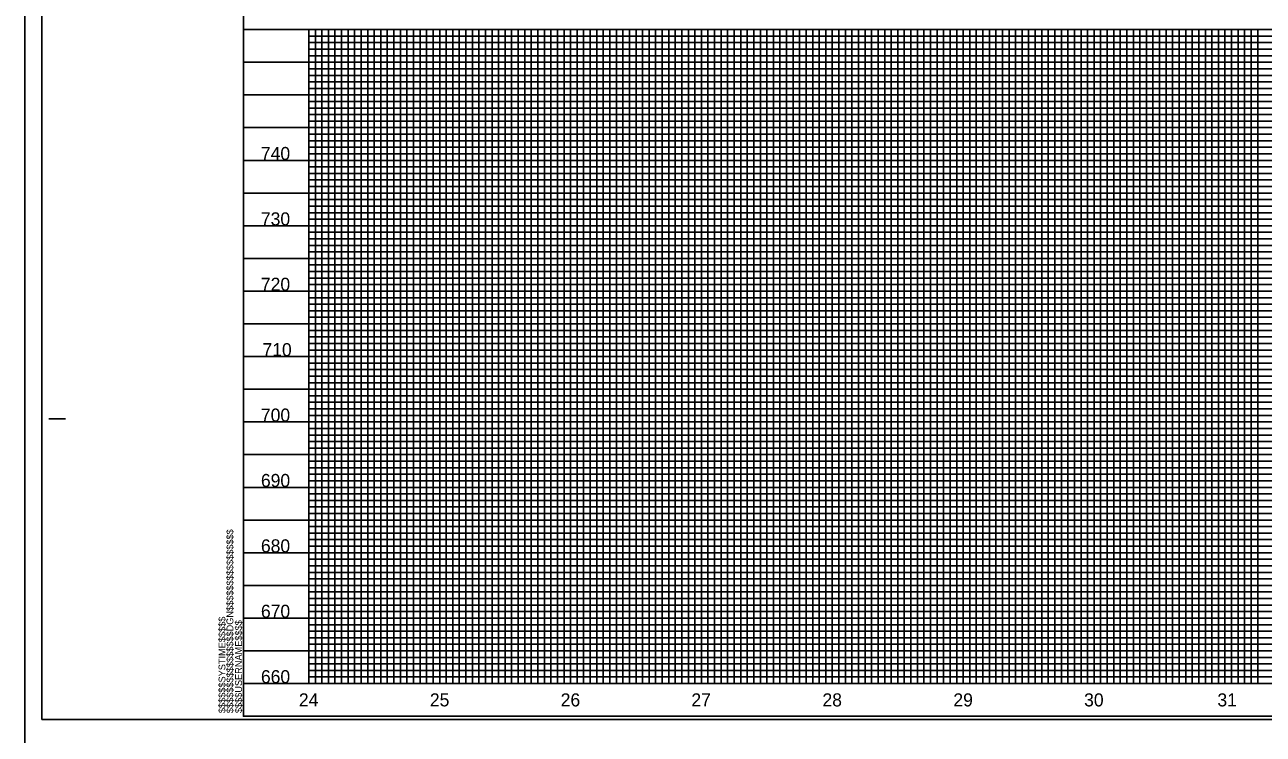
# Model space of a CAD drawing. Extents: x 1754992 to 1757273, y 732111 to 735411.
# Drawn here: x 1755181 to 1756127, y 734322 to 734864 of the extents above; entities that cross this region are included whole.
import ezdxf

# ---------------------------------------------------------------- set-up
doc = ezdxf.new("R2010")
doc.units = 0
for name, color, linetype in [('Prop DSN Text', 7, 'Continuous'), ('Scratch_Level_3', 7, 'Continuous'), ('Sheet Cutting Line CELL', 7, 'Continuous'), ('Sheet DOT Grid CELL', 7, 'Continuous'), ('Sheet Plot Border Inside CELL', 7, 'Continuous'), ('Sheet Plot Border Outside CELL', 7, 'Continuous'), ('Sheet Profile CELL', 7, 'Continuous'), ('Sheet Profile Grid Major CELL', 7, 'Continuous'), ('Sheet Profile Grid Middle CELL', 7, 'Continuous'), ('Sheet Profile Grid Minor CELL', 7, 'Continuous')]:
    doc.layers.add(name, color=color, linetype=linetype)

msp = doc.modelspace()

# ---------------------------------------------------------------- linework, layer by layer
at = {"layer": 'Scratch_Level_3'}
msp.add_lwpolyline([(1755397.67, 734860.78), (1756797.67, 734860.78), (1756797.67, 734360.78), (1755397.67, 734360.78)], close=True, dxfattribs=at)
at = {"layer": 'Sheet Cutting Line CELL'}
msp.add_line((1755180.67, 735410.78), (1755180.67, 734310.78), dxfattribs=at)
at = {"layer": 'Sheet DOT Grid CELL'}
for p, q in [((1755347.67, 734860.78), (1756847.56, 734860.78)), ((1755397.67, 734860.78), (1755397.67, 734360.78)), ((1755447.67, 734860.78), (1755447.67, 734360.78)), ((1755497.67, 734860.78), (1755497.67, 734360.78)), ((1755547.67, 734860.78), (1755547.67, 734360.78)), ((1755597.67, 734860.78), (1755597.67, 734360.78)), ((1755647.67, 734860.78), (1755647.67, 734360.78)), ((1755697.67, 734860.78), (1755697.67, 734360.78)), ((1755747.67, 734860.78), (1755747.67, 734360.78)), ((1755797.67, 734860.78), (1755797.67, 734360.78)), ((1755847.67, 734860.78), (1755847.67, 734360.78)), ((1755897.67, 734860.78), (1755897.67, 734360.78)), ((1755947.67, 734860.78), (1755947.67, 734360.78)), ((1755997.67, 734860.78), (1755997.67, 734360.78)), ((1756047.67, 734860.78), (1756047.67, 734360.78)), ((1756097.67, 734860.78), (1756097.67, 734360.78)), ((1755347.67, 734810.78), (1756847.56, 734810.78)), ((1755347.67, 734760.78), (1756847.56, 734760.78)), ((1755347.67, 734710.78), (1756847.56, 734710.78)), ((1755347.67, 734660.78), (1756847.56, 734660.78)), ((1755347.67, 734610.78), (1756847.56, 734610.78)), ((1755347.67, 734560.78), (1756847.56, 734560.78)), ((1755347.67, 734510.78), (1756847.56, 734510.78)), ((1755347.67, 734460.78), (1756847.56, 734460.78)), ((1755347.67, 734410.78), (1756847.56, 734410.78))]:
    msp.add_line(p, q, dxfattribs=at)
at = {"layer": 'Sheet Plot Border Inside CELL'}
msp.add_lwpolyline([(1755193.67, 734333.23), (1756860.17, 734333.23), (1756860.17, 735388.33), (1755193.67, 735388.33)], close=True, dxfattribs=at)
at = {"layer": 'Sheet Plot Border Outside CELL'}
msp.add_lwpolyline([(1755180.67, 734310.78), (1756864.67, 734310.78), (1756864.67, 735410.78), (1755180.67, 735410.78)], close=True, dxfattribs=at)
at = {"layer": 'Sheet Profile CELL'}
for p, q in [((1755347.67, 734860.78), (1756847.67, 734860.78)), ((1755199.17, 734563.28), (1755211.67, 734563.28)), ((1756847.67, 734360.78), (1755347.67, 734360.78)), ((1755347.67, 734335.78), (1756847.67, 734335.78)), ((1755347.67, 734335.78), (1755347.67, 734335.78)), ((1755347.67, 734335.78), (1755347.67, 734335.78)), ((1755347.67, 734335.78), (1755347.67, 734335.78)), ((1755347.67, 734335.78), (1755347.67, 734335.78)), ((1755347.67, 734335.78), (1755347.67, 734335.78)), ((1755347.67, 734335.78), (1755347.67, 734335.78)), ((1755347.67, 734335.78), (1755347.67, 734335.78))]:
    msp.add_line(p, q, dxfattribs=at)
msp.add_lwpolyline([(1756847.67, 735385.78), (1755347.67, 735385.78), (1755347.67, 734335.78), (1756847.67, 734335.78)], close=True, dxfattribs=at)
msp.add_lwpolyline([(1755385.17, 734335.78), (1755385.17, 734335.78)], dxfattribs=at)
at = {"layer": 'Sheet Profile Grid Major CELL'}
for p, q in [((1755847.67, 734860.78), (1755897.67, 734860.78)), ((1755947.67, 734860.78), (1755997.67, 734860.78)), ((1756047.67, 734860.78), (1756097.67, 734860.78)), ((1755347.67, 734360.78), (1755347.67, 734360.78))]:
    msp.add_line(p, q, dxfattribs=at)
for points in [[(1755397.67, 734860.78), (1755397.67, 734360.78), (1755447.67, 734360.78), (1755447.67, 734860.78), (1755497.67, 734860.78), (1755497.67, 734360.78), (1755547.67, 734360.78), (1755547.67, 734860.78), (1755597.67, 734860.78), (1755597.67, 734360.78), (1755647.67, 734360.78), (1755647.67, 734860.78), (1755697.67, 734860.78), (1755697.67, 734360.78), (1755747.67, 734360.78), (1755747.67, 734860.78), (1755797.67, 734860.78), (1755797.67, 734360.78), (1755847.67, 734360.78), (1755847.67, 734860.78), (1755897.67, 734860.78), (1755897.67, 734360.78), (1755947.67, 734360.78), (1755947.67, 734860.78), (1755997.67, 734860.78), (1755997.67, 734360.78), (1756047.67, 734360.78), (1756047.67, 734860.78), (1756097.67, 734860.78), (1756097.67, 734360.78), (1756147.67, 734360.78)], [(1756847.67, 734810.78), (1755347.67, 734810.78)], [(1756847.67, 734760.78), (1755347.67, 734760.78), (1755347.67, 734710.78), (1756847.67, 734710.78)], [(1756847.67, 734660.78), (1755347.67, 734660.78), (1755347.67, 734610.78), (1756847.67, 734610.78)], [(1756847.67, 734560.78), (1755347.67, 734560.78), (1755347.67, 734510.78), (1756847.67, 734510.78)], [(1756847.67, 734460.78), (1755347.67, 734460.78), (1755347.67, 734460.78), (1755347.67, 734410.78), (1756847.67, 734410.78)], [(1756847.67, 734360.78), (1755347.67, 734360.78)]]:
    msp.add_lwpolyline(points, dxfattribs=at)
at = {"layer": 'Sheet Profile Grid Middle CELL'}
for points in [[(1755372.67, 734860.78), (1755422.67, 734860.78), (1755422.67, 734360.78), (1755472.67, 734360.78), (1755472.67, 734860.78), (1755522.67, 734860.78), (1755522.67, 734360.78), (1755572.67, 734360.78), (1755572.67, 734860.78), (1755622.67, 734860.78), (1755622.67, 734360.78), (1755672.67, 734360.78), (1755672.67, 734860.78), (1755722.67, 734860.78), (1755722.67, 734360.78), (1755772.67, 734360.78), (1755772.67, 734860.78), (1755822.67, 734860.78), (1755822.67, 734360.78), (1755872.67, 734360.78), (1755872.67, 734860.78), (1755922.67, 734860.78), (1755922.67, 734360.78), (1755972.67, 734360.78), (1755972.67, 734360.78), (1755972.67, 734860.78), (1756022.67, 734860.78), (1756022.67, 734360.78), (1756072.67, 734360.78), (1756072.67, 734860.78), (1756122.67, 734860.78), (1756122.67, 734360.78), (1756172.67, 734360.78)], [(1755347.67, 734835.78), (1756847.67, 734835.78)], [(1756847.67, 734785.78), (1755347.67, 734785.78), (1755347.67, 734735.78), (1756847.67, 734735.78)], [(1756847.67, 734685.78), (1755347.67, 734685.78), (1755347.67, 734635.78), (1756847.67, 734635.78)], [(1756847.67, 734585.78), (1755347.67, 734585.78), (1755347.67, 734535.78), (1756847.67, 734535.78)], [(1756847.67, 734485.78), (1755347.67, 734485.78), (1755347.67, 734435.78), (1756847.67, 734435.78)], [(1756847.67, 734385.78), (1755347.67, 734385.78)]]:
    msp.add_lwpolyline(points, dxfattribs=at)
at = {"layer": 'Sheet Profile Grid Minor CELL'}
for p, q in [((1755397.67, 734855.78), (1756797.67, 734855.78)), ((1756797.67, 734850.78), (1755397.67, 734850.78)), ((1755397.67, 734845.78), (1756797.67, 734845.78)), ((1756797.67, 734840.78), (1755397.67, 734840.78)), ((1755397.67, 734830.78), (1756797.67, 734830.78)), ((1756797.67, 734825.78), (1755397.67, 734825.78)), ((1755397.67, 734820.78), (1756797.67, 734820.78)), ((1756797.67, 734815.78), (1755397.67, 734815.78)), ((1755397.67, 734805.78), (1756797.67, 734805.78)), ((1756797.67, 734800.78), (1755397.67, 734800.78)), ((1755397.67, 734795.78), (1756797.67, 734795.78)), ((1756797.67, 734790.78), (1755397.67, 734790.78)), ((1755397.67, 734780.78), (1756797.67, 734780.78)), ((1756797.67, 734775.78), (1755397.67, 734775.78)), ((1755397.67, 734770.78), (1756797.67, 734770.78)), ((1756797.67, 734765.78), (1755397.67, 734765.78)), ((1755397.67, 734755.78), (1756797.67, 734755.78)), ((1756797.67, 734750.78), (1755397.67, 734750.78)), ((1755397.67, 734745.78), (1756797.67, 734745.78)), ((1756797.67, 734740.78), (1755397.67, 734740.78)), ((1755397.67, 734730.78), (1756797.67, 734730.78)), ((1756797.67, 734725.78), (1755397.67, 734725.78)), ((1755397.67, 734720.78), (1756797.67, 734720.78)), ((1756797.67, 734715.78), (1755397.67, 734715.78)), ((1755397.67, 734705.78), (1756797.67, 734705.78)), ((1756797.67, 734700.78), (1755397.67, 734700.78)), ((1755397.67, 734695.78), (1756797.67, 734695.78)), ((1756797.67, 734690.78), (1755397.67, 734690.78)), ((1755397.67, 734680.78), (1756797.67, 734680.78)), ((1756797.67, 734675.78), (1755397.67, 734675.78)), ((1755397.67, 734670.78), (1756797.67, 734670.78)), ((1756797.67, 734665.78), (1755397.67, 734665.93)), ((1755397.67, 734655.78), (1756797.67, 734655.78)), ((1756797.67, 734650.78), (1755397.67, 734650.78)), ((1755397.67, 734645.78), (1756797.67, 734645.78)), ((1756797.67, 734640.78), (1755397.67, 734640.78)), ((1755397.67, 734630.78), (1756797.67, 734630.78)), ((1756797.67, 734625.78), (1755397.67, 734625.78)), ((1755397.67, 734620.78), (1756797.67, 734620.78)), ((1756797.67, 734615.78), (1755397.67, 734615.78)), ((1755397.67, 734605.78), (1756797.67, 734605.78)), ((1756797.67, 734600.78), (1755397.67, 734600.78)), ((1755397.67, 734595.78), (1756797.67, 734595.78)), ((1756797.67, 734590.78), (1755397.67, 734590.78)), ((1755397.67, 734580.78), (1756797.67, 734580.78)), ((1756797.67, 734575.78), (1755397.67, 734575.78)), ((1755397.67, 734570.78), (1756797.67, 734570.78)), ((1756797.67, 734565.78), (1755397.67, 734565.78)), ((1755397.67, 734555.78), (1756797.67, 734555.78)), ((1756797.67, 734550.78), (1755397.67, 734550.78)), ((1755397.67, 734545.78), (1756797.67, 734545.78)), ((1756797.67, 734540.78), (1755397.67, 734540.78)), ((1755397.67, 734530.78), (1756797.67, 734530.78)), ((1756797.67, 734525.78), (1755397.67, 734525.78)), ((1755397.67, 734520.78), (1756797.67, 734520.78)), ((1756797.67, 734515.78), (1755397.67, 734515.78)), ((1755397.67, 734505.78), (1756797.67, 734505.78)), ((1756797.67, 734500.78), (1755397.67, 734500.78)), ((1755397.67, 734495.78), (1756797.67, 734495.78)), ((1756797.67, 734490.78), (1755397.67, 734490.78)), ((1755397.67, 734480.78), (1756797.67, 734480.78)), ((1756797.67, 734475.78), (1755397.67, 734475.78)), ((1755397.67, 734470.78), (1756797.67, 734470.78)), ((1756797.67, 734465.78), (1755397.67, 734465.78)), ((1755397.67, 734455.78), (1756797.67, 734455.78)), ((1756797.67, 734450.78), (1755397.67, 734450.78)), ((1755397.67, 734445.78), (1756797.67, 734445.78)), ((1756797.67, 734440.78), (1755397.67, 734440.78)), ((1755397.67, 734430.78), (1756797.67, 734430.78)), ((1756797.67, 734425.78), (1755397.67, 734425.78)), ((1755397.67, 734420.78), (1756797.67, 734420.78)), ((1756797.67, 734415.78), (1755397.67, 734415.78)), ((1755397.67, 734405.78), (1756797.67, 734405.78)), ((1756797.67, 734400.78), (1755397.67, 734400.78)), ((1755397.67, 734395.78), (1756797.67, 734395.78)), ((1756797.67, 734390.78), (1755397.67, 734390.78)), ((1755397.67, 734380.78), (1756797.67, 734380.78)), ((1756797.67, 734375.78), (1755397.67, 734375.78)), ((1755397.67, 734370.78), (1756797.67, 734370.78)), ((1755397.67, 734365.78), (1756797.67, 734365.78))]:
    msp.add_line(p, q, dxfattribs=at)
for points in [[(1755397.67, 734860.78), (1755402.67, 734860.78), (1755402.67, 734360.78), (1755407.67, 734360.78), (1755407.67, 734860.78), (1755412.67, 734860.78), (1755412.67, 734360.78), (1755417.67, 734360.78), (1755417.67, 734860.78), (1755427.67, 734860.78), (1755427.67, 734360.78), (1755432.67, 734360.78), (1755432.67, 734860.78), (1755437.67, 734860.78), (1755437.67, 734360.78), (1755442.67, 734360.78), (1755452.67, 734360.78), (1755457.67, 734360.78), (1755457.67, 734860.78), (1755462.67, 734860.78), (1755462.67, 734360.78), (1755467.67, 734360.78), (1755467.67, 734860.78), (1755477.67, 734860.78), (1755477.67, 734360.78), (1755482.67, 734360.78), (1755482.67, 734860.78), (1755487.67, 734860.78), (1755487.67, 734360.78), (1755492.67, 734360.78), (1755492.67, 734860.78), (1755502.67, 734860.78), (1755502.67, 734360.78), (1755507.67, 734360.78), (1755507.67, 734860.78), (1755512.67, 734860.78), (1755512.67, 734360.78), (1755517.67, 734360.78), (1755517.67, 734860.78), (1755527.67, 734860.78), (1755527.67, 734360.78), (1755532.67, 734360.78), (1755532.67, 734860.78), (1755537.67, 734860.78), (1755537.67, 734360.78), (1755542.67, 734360.78), (1755542.67, 734860.78), (1755552.67, 734860.78), (1755552.67, 734360.78), (1755557.67, 734360.78), (1755557.67, 734860.78), (1755562.67, 734860.78), (1755562.67, 734360.78), (1755567.67, 734360.78), (1755567.67, 734860.78), (1755577.67, 734860.78), (1755577.67, 734360.78), (1755582.67, 734360.78), (1755582.67, 734860.78), (1755587.67, 734860.78), (1755587.67, 734360.78), (1755592.67, 734360.78), (1755592.67, 734860.78), (1755602.67, 734860.78), (1755602.67, 734360.78), (1755607.67, 734360.78), (1755607.67, 734860.78), (1755612.67, 734860.78), (1755612.67, 734360.78)], [(1755442.67, 734360.78), (1755442.67, 734860.78), (1755452.67, 734860.78), (1755452.67, 734360.78)], [(1755612.67, 734360.78), (1755617.67, 734360.78), (1755617.67, 734860.78), (1755627.67, 734860.78), (1755627.67, 734360.78), (1755632.67, 734360.78), (1755632.67, 734860.78), (1755637.67, 734860.78), (1755637.67, 734360.78), (1755642.67, 734360.78), (1755642.67, 734860.78), (1755652.67, 734860.78), (1755652.67, 734360.78), (1755657.67, 734360.78), (1755657.67, 734860.78), (1755662.67, 734860.78), (1755662.67, 734360.78), (1755667.67, 734360.78), (1755667.67, 734860.78), (1755677.67, 734860.78), (1755677.67, 734360.78), (1755682.67, 734360.78), (1755682.67, 734860.78), (1755687.67, 734860.78), (1755687.67, 734360.78), (1755692.67, 734360.78), (1755692.67, 734860.78), (1755702.67, 734860.78), (1755702.67, 734360.78), (1755707.67, 734360.78), (1755707.67, 734860.78), (1755712.67, 734860.78), (1755712.67, 734360.78), (1755717.67, 734360.78), (1755717.67, 734860.78), (1755727.67, 734860.78), (1755727.67, 734360.78), (1755732.67, 734360.78), (1755732.67, 734860.78), (1755737.67, 734860.78), (1755737.67, 734360.78), (1755742.67, 734360.78), (1755742.67, 734860.78), (1755752.67, 734860.78), (1755752.67, 734360.78), (1755757.67, 734360.78), (1755757.67, 734860.78), (1755762.67, 734860.78), (1755762.67, 734360.78), (1755767.67, 734360.78), (1755767.67, 734860.78), (1755777.67, 734860.78), (1755777.67, 734360.78), (1755782.67, 734360.78), (1755782.67, 734860.78), (1755787.67, 734860.78), (1755787.67, 734360.78), (1755792.67, 734360.78), (1755792.67, 734860.78), (1755802.67, 734860.78), (1755802.67, 734360.78), (1755807.67, 734360.78), (1755807.67, 734860.78), (1755812.67, 734860.78), (1755812.67, 734360.78), (1755817.67, 734360.78), (1755817.67, 734860.78), (1755827.67, 734860.78), (1755827.67, 734360.78), (1755832.67, 734360.78), (1755832.67, 734860.78), (1755837.67, 734860.78), (1755837.67, 734360.78), (1755842.67, 734360.78), (1755842.67, 734860.78), (1755852.67, 734860.78), (1755852.67, 734360.78), (1755857.67, 734360.78), (1755857.67, 734860.78), (1755862.67, 734860.78), (1755862.67, 734360.78), (1755867.67, 734360.78), (1755867.67, 734860.78), (1755877.67, 734860.78), (1755877.67, 734360.78), (1755882.67, 734360.78), (1755882.67, 734860.78), (1755887.67, 734860.78), (1755887.67, 734360.78), (1755892.67, 734360.78), (1755892.67, 734860.78), (1755902.67, 734860.78), (1755902.67, 734360.78), (1755907.67, 734360.78), (1755907.67, 734860.78), (1755912.67, 734860.78), (1755912.67, 734360.78), (1755917.67, 734360.78), (1755917.67, 734860.78), (1755927.67, 734860.78)], [(1755927.67, 734860.78), (1755927.67, 734360.78), (1755932.67, 734360.78), (1755932.67, 734860.78), (1755937.67, 734860.78), (1755937.67, 734360.78), (1755942.67, 734360.78), (1755942.67, 734860.78), (1755952.67, 734860.78), (1755952.67, 734360.78), (1755957.67, 734360.78), (1755957.67, 734860.78), (1755962.67, 734860.78), (1755962.67, 734360.78), (1755967.67, 734360.78), (1755967.67, 734860.78), (1755977.67, 734860.78), (1755977.67, 734360.78), (1755982.67, 734360.78), (1755982.67, 734860.78), (1755987.67, 734860.78), (1755987.67, 734360.78), (1755992.67, 734360.78), (1755992.67, 734860.78), (1756002.67, 734860.78), (1756002.67, 734360.78), (1756007.67, 734360.78), (1756007.67, 734860.78), (1756012.67, 734860.78), (1756012.67, 734360.78), (1756017.67, 734360.78), (1756017.67, 734860.78), (1756027.67, 734860.78), (1756027.67, 734360.78), (1756032.67, 734360.78), (1756032.67, 734860.78), (1756037.67, 734860.78), (1756037.67, 734360.78), (1756042.67, 734360.78), (1756042.67, 734860.78), (1756052.67, 734860.78), (1756052.67, 734360.78), (1756052.67, 734360.78), (1756057.67, 734360.78), (1756057.67, 734860.78), (1756062.67, 734860.78), (1756062.67, 734360.78), (1756067.67, 734360.78), (1756067.67, 734860.78), (1756077.67, 734860.78), (1756077.67, 734360.78), (1756082.67, 734360.78), (1756082.67, 734860.78), (1756087.67, 734860.78), (1756087.67, 734360.78), (1756092.67, 734360.78), (1756092.67, 734860.78), (1756102.67, 734860.78), (1756102.67, 734360.78), (1756107.67, 734360.78), (1756107.67, 734860.78), (1756112.67, 734860.78), (1756112.67, 734360.78), (1756117.67, 734360.78), (1756117.67, 734860.78), (1756127.67, 734860.78)]]:
    msp.add_lwpolyline(points, dxfattribs=at)

# ---------------------------------------------------------------- texts
at = {"layer": 'Prop DSN Text'}
for s, p in [('740', (1755361.1, 734761.03)), ('730', (1755361.1, 734711.03)), ('720', (1755361.1, 734661.03)), ('710', (1755362.3, 734611.03)), ('700', (1755361.1, 734561.03)), ('690', (1755361.1, 734511.03)), ('680', (1755361.1, 734461.03)), ('670', (1755361.1, 734411.03)), ('660', (1755361.1, 734361.03))]:
    msp.add_text(s, height=10, dxfattribs=at).set_placement(p)
at = {"layer": 'Scratch_Level_3'}
for s, p in [('24', (1755390.12, 734343.28)), ('25', (1755490.21, 734343.28)), ('26', (1755590.15, 734343.28)), ('27', (1755690.01, 734343.28)), ('28', (1755790.14, 734343.28)), ('29', (1755890.18, 734343.28)), ('30', (1755990.06, 734343.28)), ('31', (1756091.89, 734343.28))]:
    msp.add_text(s, height=10, dxfattribs=at).set_placement(p)
at = {"layer": 'Sheet Profile CELL'}
for s, p in [('$$$$$$$$$$$$$$$$DGN$$$$$$$$$$$$$$$$', (1755340.03, 734338.16)), ('$$$$$$SYSTIME$$$$$', (1755333.98, 734338.16)), ('$$$$USERNAME$$$$', (1755346.61, 734338.17))]:
    msp.add_text(s, height=5.25, rotation=90, dxfattribs=at).set_placement(p)

doc.saveas('drawing.dxf')
